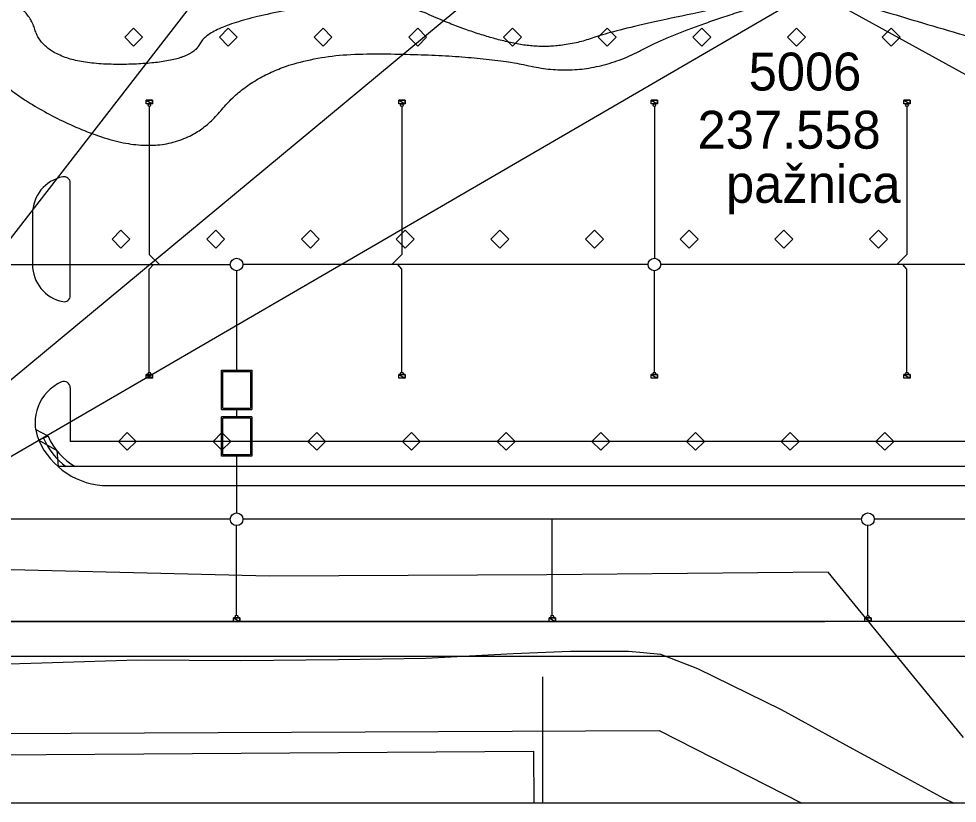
# Model space of a CAD drawing. Extents: x -264090 to -263500, y -1242327 to -1242030.
# Drawn here: x -263921.2 to -263846.8, y -1242326.6 to -1242264.5 of the extents above; entities that cross this region are included whole.
import ezdxf

# ---------------------------------------------------------------- set-up
doc = ezdxf.new("R2010")
doc.units = 0
for name, color, linetype in [('KFA_KOORD_SIT_a_IS_SEDA', 7, 'Continuous'), ('KFA_ZVS_BOD_CISLO', 7, 'Continuous'), ('KFA_ZVS_BOD_VYSKA', 7, 'Continuous'), ('KFA_ZVS_NIVELACIA', 7, 'Continuous'), ('KFA_ZVS_POPIS', 7, 'Continuous'), ('KFA_ZVS_SMERY_A_DLZKY', 7, 'Continuous'), ('RAM_NA_TLAC', 7, 'Continuous')]:
    doc.layers.add(name, color=color, linetype=linetype)

msp = doc.modelspace()

# ---------------------------------------------------------------- linework, layer by layer
at = {"layer": 'KFA_KOORD_SIT_a_IS_SEDA'}
for p, q in [((-263911.074, -1242270.983), (-263910.574, -1242270.983)), ((-263911.074, -1242271.273), (-263911.074, -1242270.983)), ((-263911.074, -1242270.983), (-263910.574, -1242271.273)), ((-263911.074, -1242270.983), (-263910.574, -1242271.273)), ((-263910.574, -1242270.983), (-263911.074, -1242270.983)), ((-263910.574, -1242270.983), (-263910.574, -1242271.273)), ((-263910.574, -1242271.273), (-263910.574, -1242270.983)), ((-263891.074, -1242270.983), (-263890.574, -1242270.983)), ((-263891.074, -1242271.273), (-263891.074, -1242270.983)), ((-263891.074, -1242270.983), (-263890.574, -1242271.273)), ((-263891.074, -1242270.983), (-263890.574, -1242271.273)), ((-263890.574, -1242270.983), (-263891.074, -1242270.983)), ((-263890.574, -1242270.983), (-263890.574, -1242271.273)), ((-263890.574, -1242271.273), (-263890.574, -1242270.983)), ((-263871.074, -1242270.983), (-263870.574, -1242270.983)), ((-263871.074, -1242271.273), (-263871.074, -1242270.983)), ((-263871.074, -1242270.983), (-263870.574, -1242271.273)), ((-263871.074, -1242270.983), (-263870.574, -1242271.273)), ((-263870.574, -1242270.983), (-263871.074, -1242270.983)), ((-263870.574, -1242270.983), (-263870.574, -1242271.273)), ((-263870.574, -1242271.273), (-263870.574, -1242270.983)), ((-263851.074, -1242270.983), (-263850.574, -1242270.983)), ((-263851.074, -1242271.273), (-263851.074, -1242270.983)), ((-263851.074, -1242270.983), (-263850.574, -1242271.273)), ((-263851.074, -1242270.983), (-263850.574, -1242271.273)), ((-263850.574, -1242270.983), (-263851.074, -1242270.983)), ((-263850.574, -1242270.983), (-263850.574, -1242271.273)), ((-263850.574, -1242271.273), (-263850.574, -1242270.983)), ((-263910.574, -1242271.273), (-263911.074, -1242271.273)), ((-263910.824, -1242271.473), (-263910.824, -1242283.187)), ((-263890.574, -1242271.273), (-263891.074, -1242271.273)), ((-263890.824, -1242271.473), (-263890.824, -1242283.187)), ((-263870.574, -1242271.273), (-263871.074, -1242271.273)), ((-263870.824, -1242271.473), (-263870.824, -1242283.482)), ((-263850.574, -1242271.273), (-263851.074, -1242271.273)), ((-263850.824, -1242271.473), (-263850.824, -1242283.187)), ((-263917.08, -1242286.432), (-263917.08, -1242277.533)), ((-263920.08, -1242279.982), (-263920.08, -1242283.982)), ((-263910.824, -1242283.187), (-263910.029, -1242283.982)), ((-263890.824, -1242283.187), (-263891.619, -1242283.982)), ((-263850.824, -1242283.187), (-263851.619, -1242283.982)), ((-263946.608, -1242283.982), (-263908.955, -1242283.982)), ((-263946.608, -1242283.982), (-263904.413, -1242283.982)), ((-263910.824, -1242284.343), (-263910.499, -1242283.982)), ((-263910.824, -1242292.492), (-263910.824, -1242284.343)), ((-263903.913, -1242284.482), (-263903.913, -1242292.347)), ((-263871.324, -1242283.982), (-263903.413, -1242283.982)), ((-263890.824, -1242284.343), (-263891.149, -1242283.982)), ((-263890.824, -1242292.492), (-263890.824, -1242284.343)), ((-263870.824, -1242292.492), (-263870.824, -1242284.482)), ((-263817.941, -1242283.982), (-263870.324, -1242283.982)), ((-263817.941, -1242283.982), (-263870.324, -1242283.982)), ((-263850.824, -1242284.343), (-263851.149, -1242283.982)), ((-263850.824, -1242292.492), (-263850.824, -1242284.343)), ((-263911.074, -1242292.692), (-263910.574, -1242292.692)), ((-263911.074, -1242292.982), (-263911.074, -1242292.692)), ((-263911.074, -1242292.692), (-263910.574, -1242292.982)), ((-263911.074, -1242292.692), (-263910.574, -1242292.982)), ((-263910.574, -1242292.692), (-263911.074, -1242292.692)), ((-263910.574, -1242292.692), (-263910.574, -1242292.982)), ((-263910.574, -1242292.982), (-263910.574, -1242292.692)), ((-263905.113, -1242292.347), (-263902.713, -1242292.347)), ((-263905.113, -1242295.447), (-263905.113, -1242292.347)), ((-263905.013, -1242292.447), (-263902.813, -1242292.447)), ((-263905.013, -1242295.347), (-263905.013, -1242292.447)), ((-263902.813, -1242292.447), (-263902.813, -1242295.347)), ((-263902.713, -1242292.347), (-263902.713, -1242295.447)), ((-263891.074, -1242292.693), (-263890.574, -1242292.693)), ((-263891.074, -1242292.983), (-263891.074, -1242292.693)), ((-263891.074, -1242292.693), (-263890.574, -1242292.983)), ((-263891.074, -1242292.693), (-263890.574, -1242292.983)), ((-263890.574, -1242292.693), (-263891.074, -1242292.693)), ((-263890.574, -1242292.693), (-263890.574, -1242292.983)), ((-263890.574, -1242292.983), (-263890.574, -1242292.693)), ((-263871.074, -1242292.693), (-263870.574, -1242292.693)), ((-263871.074, -1242292.983), (-263871.074, -1242292.693)), ((-263871.074, -1242292.693), (-263870.574, -1242292.983)), ((-263871.074, -1242292.693), (-263870.574, -1242292.983)), ((-263870.574, -1242292.693), (-263871.074, -1242292.693)), ((-263870.574, -1242292.693), (-263870.574, -1242292.983)), ((-263870.574, -1242292.983), (-263870.574, -1242292.693)), ((-263851.074, -1242292.693), (-263850.574, -1242292.693)), ((-263851.074, -1242292.983), (-263851.074, -1242292.693)), ((-263851.074, -1242292.693), (-263850.574, -1242292.983)), ((-263851.074, -1242292.693), (-263850.574, -1242292.983)), ((-263850.574, -1242292.693), (-263851.074, -1242292.693)), ((-263850.574, -1242292.693), (-263850.574, -1242292.983)), ((-263850.574, -1242292.983), (-263850.574, -1242292.693)), ((-263910.574, -1242292.982), (-263911.074, -1242292.982)), ((-263890.574, -1242292.983), (-263891.074, -1242292.983)), ((-263870.574, -1242292.983), (-263871.074, -1242292.983)), ((-263850.574, -1242292.983), (-263851.074, -1242292.983)), ((-263917.08, -1242293.737), (-263917.08, -1242297.982)), ((-263905.113, -1242295.447), (-263902.713, -1242295.447)), ((-263905.013, -1242295.347), (-263902.813, -1242295.347)), ((-263903.913, -1242295.447), (-263903.913, -1242296.047)), ((-263905.113, -1242299.147), (-263905.113, -1242296.047)), ((-263902.713, -1242296.047), (-263905.113, -1242296.047)), ((-263902.813, -1242296.147), (-263905.013, -1242296.147)), ((-263905.013, -1242299.047), (-263905.013, -1242296.147)), ((-263902.813, -1242296.147), (-263902.813, -1242299.047)), ((-263902.713, -1242296.047), (-263902.713, -1242299.147)), ((-263918.846, -1242297.562), (-263919.828, -1242297.035)), ((-263918.846, -1242297.562), (-263919.579, -1242297.882)), ((-263815.601, -1242297.982), (-263917.08, -1242297.982)), ((-263902.713, -1242299.147), (-263905.113, -1242299.147)), ((-263902.813, -1242299.047), (-263905.013, -1242299.047)), ((-263903.913, -1242299.147), (-263903.913, -1242303.647)), ((-263816.308, -1242299.982), (-263918.049, -1242299.982)), ((-263914.08, -1242301.482), (-263815.822, -1242301.482)), ((-263904.413, -1242304.147), (-263953.413, -1242304.147)), ((-263903.913, -1242311.742), (-263903.913, -1242304.647)), ((-263854.415, -1242304.147), (-263903.413, -1242304.147)), ((-263878.913, -1242311.742), (-263878.913, -1242304.147)), ((-263853.915, -1242311.749), (-263853.915, -1242304.647)), ((-263809.091, -1242304.153), (-263853.415, -1242304.148)), ((-263901.294, -1242308.658), (-263931.403, -1242307.918)), ((-263857.064, -1242308.341), (-263879.345, -1242308.544)), ((-263846.335, -1242321.415), (-263857.064, -1242308.341)), ((-263879.345, -1242308.544), (-263901.294, -1242308.658)), ((-263904.163, -1242311.942), (-263903.663, -1242311.942)), ((-263904.163, -1242312.232), (-263904.163, -1242311.942)), ((-263904.163, -1242311.942), (-263903.663, -1242312.232)), ((-263904.163, -1242311.942), (-263903.663, -1242312.232)), ((-263903.663, -1242311.942), (-263904.163, -1242311.942)), ((-263903.663, -1242311.942), (-263903.663, -1242312.232)), ((-263903.663, -1242312.232), (-263903.663, -1242311.942)), ((-263879.163, -1242311.942), (-263878.663, -1242311.942)), ((-263879.163, -1242312.232), (-263879.163, -1242311.942)), ((-263879.163, -1242311.942), (-263878.663, -1242312.232)), ((-263879.163, -1242311.942), (-263878.663, -1242312.232)), ((-263878.663, -1242311.942), (-263879.163, -1242311.942)), ((-263878.663, -1242311.942), (-263878.663, -1242312.232)), ((-263878.663, -1242312.232), (-263878.663, -1242311.942)), ((-263854.165, -1242311.949), (-263853.665, -1242311.949)), ((-263854.165, -1242312.239), (-263854.165, -1242311.949)), ((-263854.165, -1242311.949), (-263853.665, -1242312.239)), ((-263854.165, -1242311.949), (-263853.665, -1242312.239)), ((-263853.665, -1242311.949), (-263854.165, -1242311.949)), ((-263853.665, -1242311.949), (-263853.665, -1242312.239)), ((-263853.665, -1242312.239), (-263853.665, -1242311.949)), ((-263980.94, -1242312.232), (-263857.327, -1242312.232)), ((-263842.601, -1242312.24), (-263924.192, -1242312.232)), ((-263903.663, -1242312.232), (-263904.163, -1242312.232)), ((-263878.663, -1242312.232), (-263879.163, -1242312.232)), ((-263853.665, -1242312.239), (-263854.165, -1242312.239)), ((-264038.443, -1242314.982), (-263836.403, -1242314.982)), ((-263888.93, -1242315.15), (-263882, -1242314.76)), ((-263882, -1242314.76), (-263877.47, -1242314.59)), ((-263877.47, -1242314.59), (-263872.88, -1242314.58)), ((-263872.88, -1242314.58), (-263871.69, -1242314.7)), ((-263871.69, -1242314.7), (-263870.34, -1242314.83)), ((-263870.34, -1242314.83), (-263867.42, -1242315.97)), ((-263926.77, -1242315.74), (-263919.34, -1242315.51)), ((-263919.34, -1242315.51), (-263911.76, -1242315.27)), ((-263911.76, -1242315.27), (-263903.58, -1242315.33)), ((-263903.58, -1242315.33), (-263895.84, -1242315.25)), ((-263895.84, -1242315.25), (-263888.93, -1242315.15)), ((-263867.42, -1242315.97), (-263860.78, -1242319.2)), ((-263860.78, -1242319.2), (-263855.41, -1242322.16)), ((-263961.846, -1242321.299), (-263870.439, -1242320.864)), ((-263870.439, -1242320.864), (-263859.158, -1242326.619)), ((-263976.89, -1242323.14), (-263880.39, -1242322.51)), ((-263880.39, -1242322.51), (-263880.363, -1242326.619)), ((-263855.41, -1242322.16), (-263850.82, -1242324.64)), ((-263850.82, -1242324.64), (-263847.92, -1242326.23)), ((-263847.92, -1242326.23), (-263847.114, -1242326.619))]:
    msp.add_line(p, q, dxfattribs=at)
for points in [[(-263912.068, -1242265.279), (-263911.361, -1242265.986), (-263912.068, -1242266.693), (-263912.775, -1242265.986)], [(-263904.568, -1242265.279), (-263903.861, -1242265.986), (-263904.568, -1242266.693), (-263905.275, -1242265.986)], [(-263897.068, -1242265.279), (-263896.361, -1242265.986), (-263897.068, -1242266.693), (-263897.775, -1242265.986)], [(-263897.068, -1242265.279), (-263896.361, -1242265.986), (-263897.068, -1242266.693), (-263897.775, -1242265.986)], [(-263889.568, -1242265.279), (-263888.861, -1242265.986), (-263889.568, -1242266.693), (-263890.275, -1242265.986)], [(-263882.068, -1242265.279), (-263881.361, -1242265.986), (-263882.068, -1242266.693), (-263882.775, -1242265.986)], [(-263874.568, -1242265.279), (-263873.861, -1242265.986), (-263874.568, -1242266.693), (-263875.275, -1242265.986)], [(-263867.068, -1242265.279), (-263866.361, -1242265.986), (-263867.068, -1242266.693), (-263867.775, -1242265.986)], [(-263859.568, -1242265.279), (-263858.861, -1242265.986), (-263859.568, -1242266.693), (-263860.275, -1242265.986)], [(-263852.068, -1242265.279), (-263851.361, -1242265.986), (-263852.068, -1242266.693), (-263852.775, -1242265.986)], [(-263913.068, -1242281.275), (-263912.361, -1242281.982), (-263913.068, -1242282.689), (-263913.775, -1242281.982)], [(-263905.568, -1242281.275), (-263904.861, -1242281.982), (-263905.568, -1242282.689), (-263906.275, -1242281.982)], [(-263898.068, -1242281.275), (-263897.361, -1242281.982), (-263898.068, -1242282.689), (-263898.775, -1242281.982)], [(-263890.568, -1242281.275), (-263889.861, -1242281.982), (-263890.568, -1242282.689), (-263891.275, -1242281.982)], [(-263890.568, -1242281.275), (-263889.861, -1242281.982), (-263890.568, -1242282.689), (-263891.275, -1242281.982)], [(-263883.068, -1242281.275), (-263882.361, -1242281.982), (-263883.068, -1242282.689), (-263883.775, -1242281.982)], [(-263875.568, -1242281.275), (-263874.861, -1242281.982), (-263875.568, -1242282.689), (-263876.275, -1242281.982)], [(-263868.068, -1242281.275), (-263867.361, -1242281.982), (-263868.068, -1242282.689), (-263868.775, -1242281.982)], [(-263860.568, -1242281.275), (-263859.861, -1242281.982), (-263860.568, -1242282.689), (-263861.275, -1242281.982)], [(-263853.068, -1242281.275), (-263852.361, -1242281.982), (-263853.068, -1242282.689), (-263853.775, -1242281.982)], [(-263912.568, -1242297.275), (-263911.861, -1242297.982), (-263912.568, -1242298.689), (-263913.275, -1242297.982)], [(-263905.068, -1242297.275), (-263904.361, -1242297.982), (-263905.068, -1242298.689), (-263905.775, -1242297.982)], [(-263897.568, -1242297.275), (-263896.861, -1242297.982), (-263897.568, -1242298.689), (-263898.275, -1242297.982)], [(-263890.068, -1242297.275), (-263889.361, -1242297.982), (-263890.068, -1242298.689), (-263890.775, -1242297.982)], [(-263890.068, -1242297.275), (-263889.361, -1242297.982), (-263890.068, -1242298.689), (-263890.775, -1242297.982)], [(-263882.568, -1242297.275), (-263881.861, -1242297.982), (-263882.568, -1242298.689), (-263883.275, -1242297.982)], [(-263875.068, -1242297.275), (-263874.361, -1242297.982), (-263875.068, -1242298.689), (-263875.775, -1242297.982)], [(-263867.568, -1242297.275), (-263866.861, -1242297.982), (-263867.568, -1242298.689), (-263868.275, -1242297.982)], [(-263860.068, -1242297.275), (-263859.361, -1242297.982), (-263860.068, -1242298.689), (-263860.775, -1242297.982)], [(-263852.568, -1242297.275), (-263851.861, -1242297.982), (-263852.568, -1242298.689), (-263853.275, -1242297.982)]]:
    msp.add_lwpolyline(points, close=True, dxfattribs=at)
msp.add_lwpolyline([(-263919.579, -1242297.882), (-263918.155, -1242298.713), (-263918.049, -1242299.982)], dxfattribs=at)
for centre, radius in [((-263910.824, -1242271.373), 0.1), ((-263890.824, -1242271.373), 0.1), ((-263870.824, -1242271.373), 0.1), ((-263850.824, -1242271.373), 0.1), ((-263903.913, -1242283.982), 0.5), ((-263870.824, -1242283.982), 0.5), ((-263910.824, -1242292.592), 0.1), ((-263890.824, -1242292.592), 0.1), ((-263870.824, -1242292.592), 0.1), ((-263850.824, -1242292.592), 0.1), ((-263903.913, -1242304.147), 0.5), ((-263853.915, -1242304.147), 0.5), ((-263903.913, -1242311.842), 0.1), ((-263878.913, -1242311.842), 0.1), ((-263853.915, -1242311.849), 0.1)]:
    msp.add_circle(centre, radius, dxfattribs=at)
for centre, radius, start, end in [((-263917.08, -1242279.982), 3, 101.53696, 180), ((-263917.58, -1242277.533), 0.5, 0, 101.53696), ((-263917.08, -1242283.982), 3, 180, 258.46304), ((-263917.58, -1242286.432), 0.5, 258.46304, 0), ((-263916.372, -1242296.482), 3.5, 113.75985, 203.57818), ((-263917.58, -1242293.737), 0.5, 0, 113.75985), ((-263914.08, -1242295.482), 6, 203.57818, 270), ((-263914.08, -1242295.482), 5.6, 203.57818, 233.47251), ((-263914.08, -1242295.482), 5.2, 203.57818, 239.92665)]:
    msp.add_arc(centre, radius, start, end, dxfattribs=at)
at = {"layer": 'KFA_ZVS_NIVELACIA'}
for points in [[(-263858.267, -1242262.294), (-263841.114, -1242267.349), (-263818.619, -1242274.1), (-263806.023, -1242261.048), (-263788.027, -1242252.947), (-263786.209, -1242248.09)], [(-263786.209, -1242248.09), (-263795.902, -1242250.777), (-263812.257, -1242253.765), (-263813.285, -1242260.917), (-263826.243, -1242266.167), (-263840.835, -1242262.689), (-263851.435, -1242261.26), (-263858.267, -1242262.294)], [(-263937.6, -1242258.211), (-263928.936, -1242262.063), (-263922.038, -1242271.064), (-263908.691, -1242276.165), (-263901.493, -1242267.314), (-263884.997, -1242267.314), (-263876.149, -1242269.264), (-263867.589, -1242264.788), (-263858.267, -1242262.294)], [(-263858.267, -1242262.294), (-263872.503, -1242264.923), (-263878.722, -1242267.127), (-263884.99, -1242265.854), (-263892.335, -1242262.572), (-263906.067, -1242264.914), (-263907.585, -1242268.147), (-263919.043, -1242268.147), (-263920.708, -1242262.66), (-263931.12, -1242259.749), (-263937.6, -1242258.211)]]:
    msp.add_open_spline(points, degree=2, dxfattribs=at)
at = {"layer": 'KFA_ZVS_SMERY_A_DLZKY'}
for p, q in [((-263779.166, -1242098.021), (-263946.283, -1242313.43)), ((-263768.002, -1242165.53), (-263946.283, -1242313.43)), ((-263858.267, -1242262.294), (-263946.283, -1242313.43)), ((-263858.267, -1242262.294), (-263765.994, -1242313.054))]:
    msp.add_line(p, q, dxfattribs=at)
at = {"layer": 'RAM_NA_TLAC'}
msp.add_line((-263879.658, -1242326.619), (-263879.658, -1242316.619), dxfattribs=at)
msp.add_lwpolyline([(-264089.658, -1242029.619), (-263499.658, -1242029.619), (-263499.658, -1242326.619), (-264089.658, -1242326.619)], close=True, dxfattribs=at)

# ---------------------------------------------------------------- texts
at = {"layer": 'KFA_ZVS_BOD_CISLO'}
msp.add_text('5006', height=3, dxfattribs=at).set_placement((-263863.359, -1242270.212))
at = {"layer": 'KFA_ZVS_BOD_VYSKA'}
msp.add_text('237.558', height=3, dxfattribs=at).set_placement((-263867.405, -1242274.817))
at = {"layer": 'KFA_ZVS_POPIS'}
msp.add_text('pažnica', height=3, dxfattribs=at).set_placement((-263865.152, -1242279.102))

doc.saveas('drawing.dxf')
